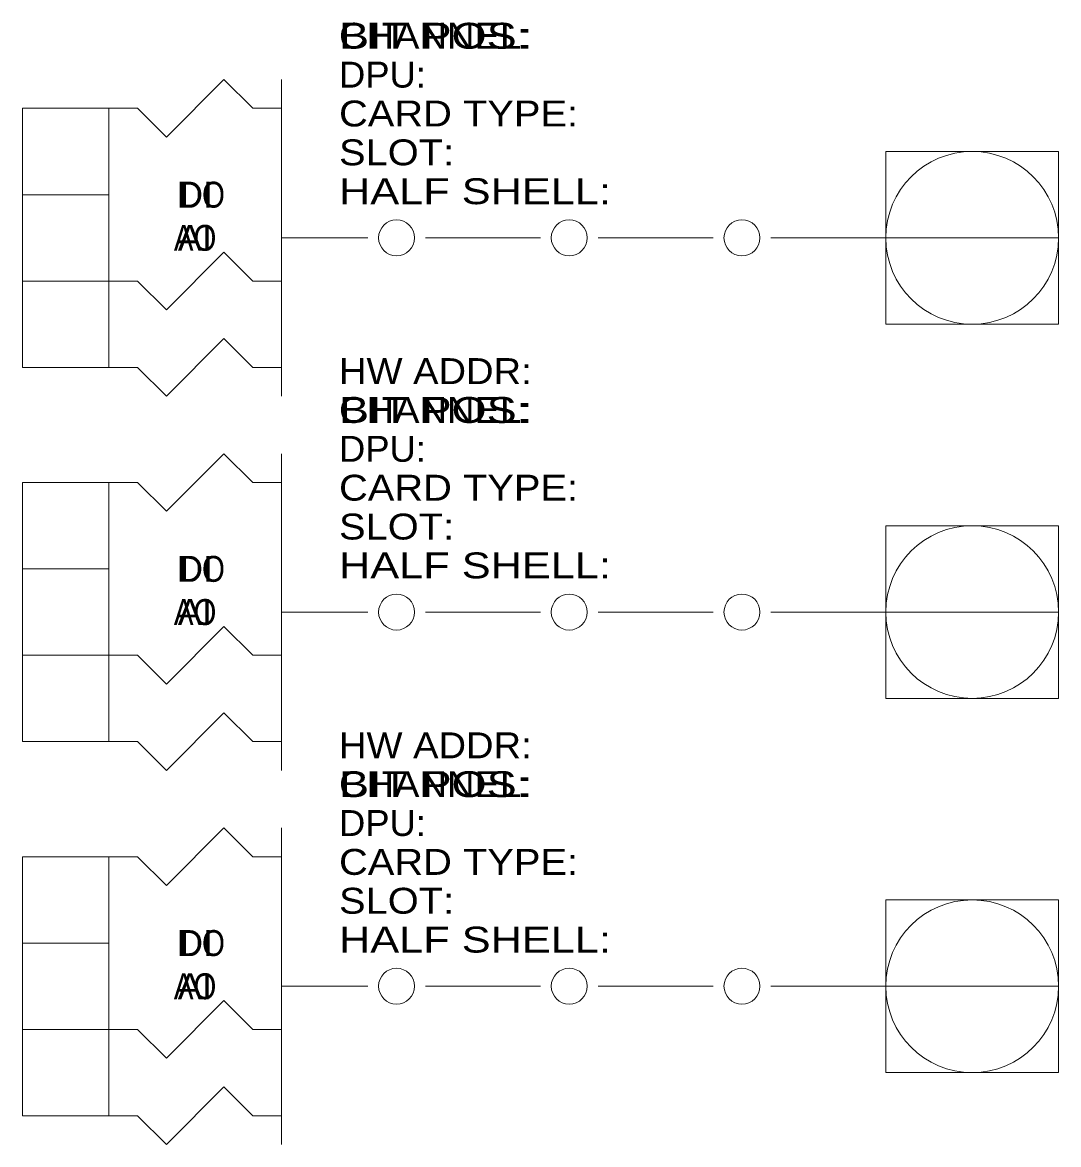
# Model space of a CAD drawing. Extents: x 0.958 to 1.258, y 0.171 to 0.832.
# Drawn here: x 0.9583 to 1.2583, y 0.1708 to 0.4957 of the extents above; entities that cross this region are included whole.
import ezdxf
from ezdxf.enums import TextEntityAlignment as Align

# ---------------------------------------------------------------- set-up
doc = ezdxf.new("R2010")
doc.units = 0
doc.header["$LTSCALE"] = 0.003
for name, color, linetype, lineweight in [('31', 7, 'Continuous', 13), ('32', 7, 'Continuous', 13), ('33', 7, 'Continuous', 13), ('34', 7, 'Continuous', 13), ('39', 7, 'Continuous', 13), ('40', 7, 'Continuous', 13), ('41', 7, 'Continuous', 13), ('42', 7, 'Continuous', 13), ('43', 7, 'Continuous', 13), ('44', 7, 'Continuous', 13), ('49', 7, 'Continuous', 13), ('50', 7, 'Continuous', 13), ('51', 7, 'Continuous', 13), ('52', 7, 'Continuous', 13), ('53', 7, 'Continuous', 13), ('54', 7, 'Continuous', 13), ('59', 7, 'Continuous', 13), ('60', 7, 'Continuous', 13)]:
    doc.layers.add(name, color=color, linetype=linetype, lineweight=lineweight)

msp = doc.modelspace()

# ---------------------------------------------------------------- linework, layer by layer
at = {"layer": '31'}
msp.add_line((1.033333, 0.479166), (1.033333, 0.4125), dxfattribs=at)
for points in [[(0.983333, 0.470833), (0.991666, 0.470833), (1, 0.4625), (1.016666, 0.479166), (1.025, 0.470833), (1.033333, 0.470833)], [(0.958333, 0.445833), (0.958333, 0.420833), (0.983333, 0.420833), (0.983333, 0.445833)], [(0.983333, 0.420833), (0.991666, 0.420833), (1, 0.4125), (1.016666, 0.429166), (1.025, 0.420833), (1.033333, 0.420833)]]:
    msp.add_lwpolyline(points, dxfattribs=at)
msp.add_lwpolyline([(0.958333, 0.470833), (0.983333, 0.470833), (0.983333, 0.445833), (0.958333, 0.445833)], close=True, dxfattribs=at)
at = {"layer": '32'}
for p, q in [((1.033333, 0.479166), (1.033333, 0.4125)), ((0.958333, 0.445833), (0.983333, 0.445833))]:
    msp.add_line(p, q, dxfattribs=at)
for points in [[(0.983333, 0.470833), (0.991666, 0.470833), (1, 0.4625), (1.016666, 0.479166), (1.025, 0.470833), (1.033333, 0.470833)], [(0.983333, 0.420833), (0.991666, 0.420833), (1, 0.4125), (1.016666, 0.429166), (1.025, 0.420833), (1.033333, 0.420833)]]:
    msp.add_lwpolyline(points, dxfattribs=at)
msp.add_lwpolyline([(0.958333, 0.470833), (0.983333, 0.470833), (0.983333, 0.420833), (0.958333, 0.420833)], close=True, dxfattribs=at)
at = {"layer": '33'}
for p, q in [((1.033333, 0.3875), (1.033333, 0.479166)), ((0.958333, 0.445833), (0.983333, 0.445833)), ((0.958333, 0.420833), (0.983333, 0.420833))]:
    msp.add_line(p, q, dxfattribs=at)
for points in [[(0.983333, 0.470833), (0.991666, 0.470833), (1, 0.4625), (1.016666, 0.479166), (1.025, 0.470833), (1.033333, 0.470833)], [(0.983333, 0.395833), (0.991666, 0.395833), (1, 0.3875), (1.016666, 0.404166), (1.025, 0.395833), (1.033333, 0.395833)]]:
    msp.add_lwpolyline(points, dxfattribs=at)
msp.add_lwpolyline([(0.958333, 0.470833), (0.983333, 0.470833), (0.983333, 0.395833), (0.958333, 0.395833)], close=True, dxfattribs=at)
at = {"layer": '34'}
for p, q in [((1.033333, 0.3875), (1.033333, 0.479166)), ((0.958333, 0.445833), (0.983333, 0.445833)), ((0.958333, 0.420833), (0.983333, 0.420833))]:
    msp.add_line(p, q, dxfattribs=at)
for points in [[(0.983333, 0.470833), (0.991666, 0.470833), (1, 0.4625), (1.016666, 0.479166), (1.025, 0.470833), (1.033333, 0.470833)], [(0.983333, 0.395833), (0.991666, 0.395833), (1, 0.3875), (1.016666, 0.404166), (1.025, 0.395833), (1.033333, 0.395833)]]:
    msp.add_lwpolyline(points, dxfattribs=at)
msp.add_lwpolyline([(0.958333, 0.470833), (0.983333, 0.470833), (0.983333, 0.395833), (0.958333, 0.395833)], close=True, dxfattribs=at)
at = {"layer": '39'}
for p, q in [((1.058333, 0.433333), (1.033333, 0.433333)), ((1.108333, 0.433333), (1.075, 0.433333)), ((1.158333, 0.433333), (1.125, 0.433333)), ((1.208333, 0.433333), (1.175, 0.433333)), ((1.208333, 0.433333), (1.258333, 0.433333))]:
    msp.add_line(p, q, dxfattribs=at)
msp.add_lwpolyline([(1.208333, 0.458333), (1.208333, 0.408333), (1.258333, 0.408333), (1.258333, 0.458333)], close=True, dxfattribs=at)
for centre, radius in [((1.233333, 0.433333), 0.025), ((1.066666, 0.433333), 0.005208), ((1.116666, 0.433333), 0.005208), ((1.166666, 0.433333), 0.005208)]:
    msp.add_circle(centre, radius, dxfattribs=at)
at = {"layer": '40'}
for p, q in [((1.058333, 0.433333), (1.033333, 0.433333)), ((1.108333, 0.433333), (1.075, 0.433333)), ((1.158333, 0.433333), (1.125, 0.433333)), ((1.208333, 0.433333), (1.175, 0.433333)), ((1.208333, 0.433333), (1.258333, 0.433333))]:
    msp.add_line(p, q, dxfattribs=at)
msp.add_lwpolyline([(1.208333, 0.458333), (1.208333, 0.408333), (1.258333, 0.408333), (1.258333, 0.458333)], close=True, dxfattribs=at)
for centre, radius in [((1.233333, 0.433333), 0.025), ((1.066666, 0.433333), 0.005208), ((1.116666, 0.433333), 0.005208), ((1.166666, 0.433333), 0.005208)]:
    msp.add_circle(centre, radius, dxfattribs=at)
at = {"layer": '41'}
msp.add_line((1.033333, 0.370833), (1.033333, 0.304166), dxfattribs=at)
for points in [[(0.983333, 0.3625), (0.991666, 0.3625), (1, 0.354166), (1.016666, 0.370833), (1.025, 0.3625), (1.033333, 0.3625)], [(0.958333, 0.3375), (0.958333, 0.3125), (0.983333, 0.3125), (0.983333, 0.3375)], [(0.983333, 0.3125), (0.991666, 0.3125), (1, 0.304166), (1.016666, 0.320833), (1.025, 0.3125), (1.033333, 0.3125)]]:
    msp.add_lwpolyline(points, dxfattribs=at)
msp.add_lwpolyline([(0.958333, 0.3625), (0.983333, 0.3625), (0.983333, 0.3375), (0.958333, 0.3375)], close=True, dxfattribs=at)
at = {"layer": '42'}
for p, q in [((1.033333, 0.370833), (1.033333, 0.304166)), ((0.958333, 0.3375), (0.983333, 0.3375))]:
    msp.add_line(p, q, dxfattribs=at)
for points in [[(0.983333, 0.3625), (0.991666, 0.3625), (1, 0.354166), (1.016666, 0.370833), (1.025, 0.3625), (1.033333, 0.3625)], [(0.983333, 0.3125), (0.991666, 0.3125), (1, 0.304166), (1.016666, 0.320833), (1.025, 0.3125), (1.033333, 0.3125)]]:
    msp.add_lwpolyline(points, dxfattribs=at)
msp.add_lwpolyline([(0.958333, 0.3625), (0.983333, 0.3625), (0.983333, 0.3125), (0.958333, 0.3125)], close=True, dxfattribs=at)
at = {"layer": '43'}
for p, q in [((1.033333, 0.279166), (1.033333, 0.370833)), ((0.958333, 0.3375), (0.983333, 0.3375)), ((0.958333, 0.3125), (0.983333, 0.3125))]:
    msp.add_line(p, q, dxfattribs=at)
for points in [[(0.983333, 0.3625), (0.991666, 0.3625), (1, 0.354166), (1.016666, 0.370833), (1.025, 0.3625), (1.033333, 0.3625)], [(0.983333, 0.2875), (0.991666, 0.2875), (1, 0.279166), (1.016666, 0.295833), (1.025, 0.2875), (1.033333, 0.2875)]]:
    msp.add_lwpolyline(points, dxfattribs=at)
msp.add_lwpolyline([(0.958333, 0.3625), (0.983333, 0.3625), (0.983333, 0.2875), (0.958333, 0.2875)], close=True, dxfattribs=at)
at = {"layer": '44'}
for p, q in [((1.033333, 0.279166), (1.033333, 0.370833)), ((0.958333, 0.3375), (0.983333, 0.3375)), ((0.958333, 0.3125), (0.983333, 0.3125))]:
    msp.add_line(p, q, dxfattribs=at)
for points in [[(0.983333, 0.3625), (0.991666, 0.3625), (1, 0.354166), (1.016666, 0.370833), (1.025, 0.3625), (1.033333, 0.3625)], [(0.983333, 0.2875), (0.991666, 0.2875), (1, 0.279166), (1.016666, 0.295833), (1.025, 0.2875), (1.033333, 0.2875)]]:
    msp.add_lwpolyline(points, dxfattribs=at)
msp.add_lwpolyline([(0.958333, 0.3625), (0.983333, 0.3625), (0.983333, 0.2875), (0.958333, 0.2875)], close=True, dxfattribs=at)
at = {"layer": '49'}
for p, q in [((1.058333, 0.325), (1.033333, 0.325)), ((1.108333, 0.325), (1.075, 0.325)), ((1.158333, 0.325), (1.125, 0.325)), ((1.208333, 0.325), (1.175, 0.325)), ((1.208333, 0.325), (1.258333, 0.325))]:
    msp.add_line(p, q, dxfattribs=at)
msp.add_lwpolyline([(1.208333, 0.35), (1.208333, 0.3), (1.258333, 0.3), (1.258333, 0.35)], close=True, dxfattribs=at)
for centre, radius in [((1.233333, 0.325), 0.025), ((1.066666, 0.325), 0.005208), ((1.116666, 0.325), 0.005208), ((1.166666, 0.325), 0.005208)]:
    msp.add_circle(centre, radius, dxfattribs=at)
at = {"layer": '50'}
for p, q in [((1.058333, 0.325), (1.033333, 0.325)), ((1.108333, 0.325), (1.075, 0.325)), ((1.158333, 0.325), (1.125, 0.325)), ((1.208333, 0.325), (1.175, 0.325)), ((1.208333, 0.325), (1.258333, 0.325))]:
    msp.add_line(p, q, dxfattribs=at)
msp.add_lwpolyline([(1.208333, 0.35), (1.208333, 0.3), (1.258333, 0.3), (1.258333, 0.35)], close=True, dxfattribs=at)
for centre, radius in [((1.233333, 0.325), 0.025), ((1.066666, 0.325), 0.005208), ((1.116666, 0.325), 0.005208), ((1.166666, 0.325), 0.005208)]:
    msp.add_circle(centre, radius, dxfattribs=at)
at = {"layer": '51'}
msp.add_line((1.033333, 0.2625), (1.033333, 0.195833), dxfattribs=at)
for points in [[(0.983333, 0.254166), (0.991666, 0.254166), (1, 0.245833), (1.016666, 0.2625), (1.025, 0.254166), (1.033333, 0.254166)], [(0.958333, 0.229166), (0.958333, 0.204166), (0.983333, 0.204166), (0.983333, 0.229166)], [(0.983333, 0.204166), (0.991666, 0.204166), (1, 0.195833), (1.016666, 0.2125), (1.025, 0.204166), (1.033333, 0.204166)]]:
    msp.add_lwpolyline(points, dxfattribs=at)
msp.add_lwpolyline([(0.958333, 0.254166), (0.983333, 0.254166), (0.983333, 0.229166), (0.958333, 0.229166)], close=True, dxfattribs=at)
at = {"layer": '52'}
for p, q in [((1.033333, 0.2625), (1.033333, 0.195833)), ((0.958333, 0.229166), (0.983333, 0.229166))]:
    msp.add_line(p, q, dxfattribs=at)
for points in [[(0.983333, 0.254166), (0.991666, 0.254166), (1, 0.245833), (1.016666, 0.2625), (1.025, 0.254166), (1.033333, 0.254166)], [(0.983333, 0.204166), (0.991666, 0.204166), (1, 0.195833), (1.016666, 0.2125), (1.025, 0.204166), (1.033333, 0.204166)]]:
    msp.add_lwpolyline(points, dxfattribs=at)
msp.add_lwpolyline([(0.958333, 0.254166), (0.983333, 0.254166), (0.983333, 0.204166), (0.958333, 0.204166)], close=True, dxfattribs=at)
at = {"layer": '53'}
for p, q in [((1.033333, 0.170833), (1.033333, 0.2625)), ((0.958333, 0.229166), (0.983333, 0.229166)), ((0.958333, 0.204166), (0.983333, 0.204166))]:
    msp.add_line(p, q, dxfattribs=at)
for points in [[(0.983333, 0.254166), (0.991666, 0.254166), (1, 0.245833), (1.016666, 0.2625), (1.025, 0.254166), (1.033333, 0.254166)], [(0.983333, 0.179166), (0.991666, 0.179166), (1, 0.170833), (1.016666, 0.1875), (1.025, 0.179166), (1.033333, 0.179166)]]:
    msp.add_lwpolyline(points, dxfattribs=at)
msp.add_lwpolyline([(0.958333, 0.254166), (0.983333, 0.254166), (0.983333, 0.179166), (0.958333, 0.179166)], close=True, dxfattribs=at)
at = {"layer": '54'}
for p, q in [((1.033333, 0.170833), (1.033333, 0.2625)), ((0.958333, 0.229166), (0.983333, 0.229166)), ((0.958333, 0.204166), (0.983333, 0.204166))]:
    msp.add_line(p, q, dxfattribs=at)
for points in [[(0.983333, 0.254166), (0.991666, 0.254166), (1, 0.245833), (1.016666, 0.2625), (1.025, 0.254166), (1.033333, 0.254166)], [(0.983333, 0.179166), (0.991666, 0.179166), (1, 0.170833), (1.016666, 0.1875), (1.025, 0.179166), (1.033333, 0.179166)]]:
    msp.add_lwpolyline(points, dxfattribs=at)
msp.add_lwpolyline([(0.958333, 0.254166), (0.983333, 0.254166), (0.983333, 0.179166), (0.958333, 0.179166)], close=True, dxfattribs=at)
at = {"layer": '59'}
for p, q in [((1.058333, 0.216666), (1.033333, 0.216666)), ((1.108333, 0.216666), (1.075, 0.216666)), ((1.158333, 0.216666), (1.125, 0.216666)), ((1.208333, 0.216666), (1.175, 0.216666)), ((1.208333, 0.216666), (1.258333, 0.216666))]:
    msp.add_line(p, q, dxfattribs=at)
msp.add_lwpolyline([(1.208333, 0.241666), (1.208333, 0.191666), (1.258333, 0.191666), (1.258333, 0.241666)], close=True, dxfattribs=at)
for centre, radius in [((1.233333, 0.216666), 0.025), ((1.066666, 0.216666), 0.005208), ((1.116666, 0.216666), 0.005208), ((1.166666, 0.216666), 0.005208)]:
    msp.add_circle(centre, radius, dxfattribs=at)
at = {"layer": '60'}
for p, q in [((1.058333, 0.216666), (1.033333, 0.216666)), ((1.108333, 0.216666), (1.075, 0.216666)), ((1.158333, 0.216666), (1.125, 0.216666)), ((1.208333, 0.216666), (1.175, 0.216666)), ((1.208333, 0.216666), (1.258333, 0.216666))]:
    msp.add_line(p, q, dxfattribs=at)
msp.add_lwpolyline([(1.208333, 0.241666), (1.208333, 0.191666), (1.258333, 0.191666), (1.258333, 0.241666)], close=True, dxfattribs=at)
for centre, radius in [((1.233333, 0.216666), 0.025), ((1.066666, 0.216666), 0.005208), ((1.116666, 0.216666), 0.005208), ((1.166666, 0.216666), 0.005208)]:
    msp.add_circle(centre, radius, dxfattribs=at)

# ---------------------------------------------------------------- texts
at = {"layer": '31', "width": 1.05}
msp.add_text('DI', height=0.0075, dxfattribs=at).set_placement((1.008291, 0.442083), align=Align.CENTER)
at = {"layer": '32', "width": 0.85}
msp.add_text('DO', height=0.0075, dxfattribs=at).set_placement((1.004166, 0.442083))
at = {"layer": '33', "width": 1.05}
msp.add_text('AI', height=0.0075, dxfattribs=at).set_placement((1.008291, 0.429583), align=Align.CENTER)
at = {"layer": '34', "width": 0.85}
msp.add_text('AO', height=0.0075, dxfattribs=at).set_placement((1.008333, 0.429583), align=Align.CENTER)
at = {"layer": '39'}
for s, width, p in [('BIT POS:', 1.3, (1.05, 0.488083)), ('DPU:', 1.05, (1.05, 0.476833)), ('CARD TYPE:', 1.15, (1.05, 0.465583)), ('SLOT:', 1.15, (1.05, 0.454333)), ('HALF SHELL:', 1.25, (1.05, 0.443083))]:
    msp.add_text(s, height=0.0075, dxfattribs=dict(at, width=width)).set_placement(p)
at = {"layer": '40'}
for s, width, p in [('CHANNEL:', 1.1, (1.05, 0.488083)), ('DPU:', 1.05, (1.05, 0.476833)), ('CARD TYPE:', 1.15, (1.05, 0.465583)), ('SLOT:', 1.15, (1.05, 0.454333)), ('HALF SHELL:', 1.25, (1.05, 0.443083))]:
    msp.add_text(s, height=0.0075, dxfattribs=dict(at, width=width)).set_placement(p)
at = {"layer": '41', "width": 1.05}
msp.add_text('DI', height=0.0075, dxfattribs=at).set_placement((1.008291, 0.33375), align=Align.CENTER)
at = {"layer": '42', "width": 0.85}
msp.add_text('DO', height=0.0075, dxfattribs=at).set_placement((1.004166, 0.33375))
at = {"layer": '43', "width": 1.05}
msp.add_text('AI', height=0.0075, dxfattribs=at).set_placement((1.008291, 0.32125), align=Align.CENTER)
at = {"layer": '44', "width": 0.85}
msp.add_text('AO', height=0.0075, dxfattribs=at).set_placement((1.008333, 0.32125), align=Align.CENTER)
at = {"layer": '49'}
for s, width, p in [('HW ADDR:', 1.1, (1.05, 0.391)), ('BIT POS:', 1.3, (1.05, 0.37975)), ('DPU:', 1.05, (1.05, 0.3685)), ('CARD TYPE:', 1.15, (1.05, 0.35725)), ('SLOT:', 1.15, (1.05, 0.346)), ('HALF SHELL:', 1.25, (1.05, 0.33475))]:
    msp.add_text(s, height=0.0075, dxfattribs=dict(at, width=width)).set_placement(p)
at = {"layer": '50'}
for s, width, p in [('HW ADDR:', 1.1, (1.05, 0.391)), ('CHANNEL:', 1.1, (1.05, 0.37975)), ('DPU:', 1.05, (1.05, 0.3685)), ('CARD TYPE:', 1.15, (1.05, 0.35725)), ('SLOT:', 1.15, (1.05, 0.346)), ('HALF SHELL:', 1.25, (1.05, 0.33475))]:
    msp.add_text(s, height=0.0075, dxfattribs=dict(at, width=width)).set_placement(p)
at = {"layer": '51', "width": 1.05}
msp.add_text('DI', height=0.0075, dxfattribs=at).set_placement((1.008291, 0.225416), align=Align.CENTER)
at = {"layer": '52', "width": 0.85}
msp.add_text('DO', height=0.0075, dxfattribs=at).set_placement((1.004166, 0.225416))
at = {"layer": '53', "width": 1.05}
msp.add_text('AI', height=0.0075, dxfattribs=at).set_placement((1.008291, 0.212916), align=Align.CENTER)
at = {"layer": '54', "width": 0.85}
msp.add_text('AO', height=0.0075, dxfattribs=at).set_placement((1.008333, 0.212916), align=Align.CENTER)
at = {"layer": '59'}
for s, width, p in [('HW ADDR:', 1.1, (1.05, 0.282666)), ('BIT POS:', 1.3, (1.05, 0.271416)), ('DPU:', 1.05, (1.05, 0.260166)), ('CARD TYPE:', 1.15, (1.05, 0.248916)), ('SLOT:', 1.15, (1.05, 0.237666)), ('HALF SHELL:', 1.25, (1.05, 0.226416))]:
    msp.add_text(s, height=0.0075, dxfattribs=dict(at, width=width)).set_placement(p)
at = {"layer": '60'}
for s, width, p in [('HW ADDR:', 1.1, (1.05, 0.282666)), ('CHANNEL:', 1.1, (1.05, 0.271416)), ('DPU:', 1.05, (1.05, 0.260166)), ('CARD TYPE:', 1.15, (1.05, 0.248916)), ('SLOT:', 1.15, (1.05, 0.237666)), ('HALF SHELL:', 1.25, (1.05, 0.226416))]:
    msp.add_text(s, height=0.0075, dxfattribs=dict(at, width=width)).set_placement(p)

doc.saveas('drawing.dxf')
